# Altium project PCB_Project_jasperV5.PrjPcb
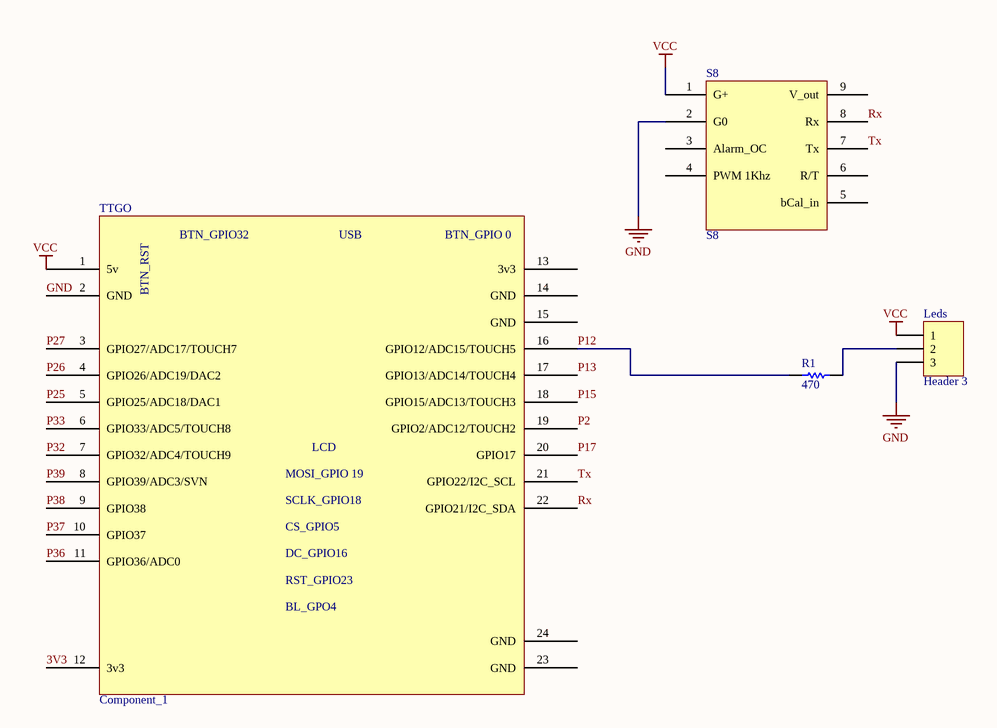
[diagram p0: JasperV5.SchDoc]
1 sheet, 4 parts. Net scope: global (net labels, ports and power ports of the same name join across sheets).
Board file: PCB_Jasperv5.PcbDoc

## Sheet JasperV5.SchDoc: Jasper
size A4; Author: Hanane Meliani; CompanyName: Centralesupelec; Revision: 5; SheetNumber: 1; SheetTotal: 1

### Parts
Leds  Header 3  [HDR1X3]
R1  value 470  [AXIAL-0.3]  (hidden comment: Res1)
S8  S8  [S8]
TTGO  Component_1  [TTGO]

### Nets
GND: Leds.3 S8.2(G0) TTGO.2(GND)
VCC: Leds.1 S8.1(G+) TTGO.1(5v)
3V3: TTGO.12(3v3)
P2: TTGO.19(GPIO2/ADC12/TOUCH2)
P12: R1.1 TTGO.16(GPIO12/ADC15/TOUCH5)
P13: TTGO.17(GPIO13/ADC14/TOUCH4)
P15: TTGO.18(GPIO15/ADC13/TOUCH3)
P17: TTGO.20(GPIO17)
P25: TTGO.5(GPIO25/ADC18/DAC1)
P26: TTGO.4(GPIO26/ADC19/DAC2)
P27: TTGO.3(GPIO27/ADC17/TOUCH7)
P32: TTGO.7(GPIO32/ADC4/TOUCH9)
P33: TTGO.6(GPIO33/ADC5/TOUCH8)
P36: TTGO.11(GPIO36/ADC0)
P37: TTGO.10(GPIO37)
P38: TTGO.9(GPIO38)
P39: TTGO.8(GPIO39/ADC3/SVN)
Rx: S8.8(Rx) TTGO.22(GPIO21/I2C_SDA)
Tx: S8.7(Tx) TTGO.21(GPIO22/I2C_SCL)
NetLeds_2: Leds.2 R1.2

Not connected (* = marked no-connect by the designer): S8 3(Alarm_OC) 4(PWM_1Khz) 5(bCal_in) 6(R/T) 9(V_out); TTGO 13(3v3) 14(GND) 15(GND) 23(GND) 24(GND)

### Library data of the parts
Leds = CMP-012-000090-1: Header, 3-Pin; Signal Integrity: Connector
R1 = CMP-025-000011-1: Resistor; Signal Integrity: Res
